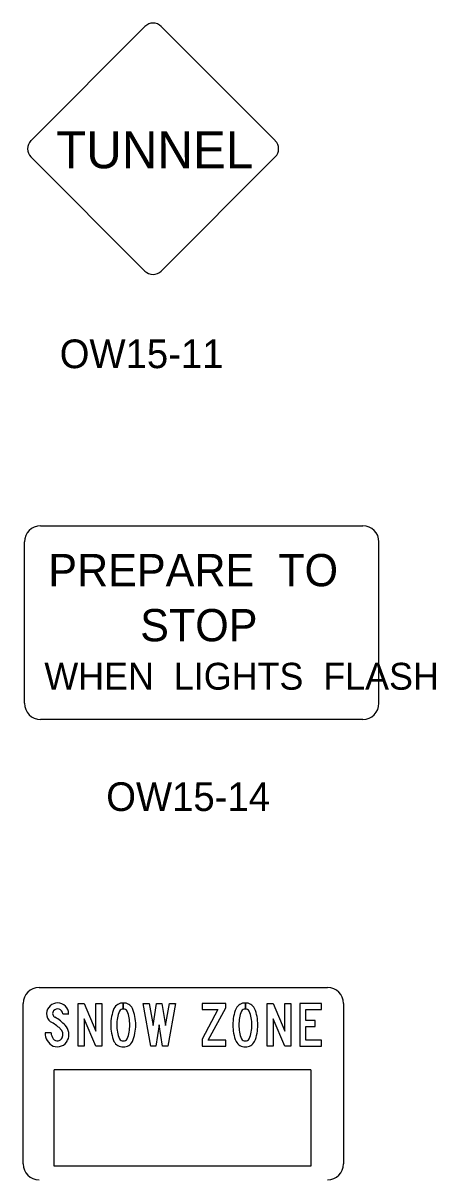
# Model space of a CAD drawing. Extents: x 42133 to 45533, y 41351 to 47951.
# Drawn here: x 43422.4 to 43530.5, y 43897.4 to 44200.2 of the extents above; entities that cross this region are included whole.
import ezdxf

# ---------------------------------------------------------------- set-up
doc = ezdxf.new("R2010")
doc.units = 0
doc.layers.add('P_TRAF_SIGN_SignDetails', color=7, linetype='Continuous')

msp = doc.modelspace()

# ---------------------------------------------------------------- linework, layer by layer
at = {"layer": 'P_TRAF_SIGN_SignDetails'}
for p, q in [((43454.29, 44199.28), (43424.42, 44169.4)), ((43488.43, 44169.41), (43458.56, 44199.29)), ((43424.42, 44165.14), (43454.29, 44135.27)), ((43458.56, 44135.27), (43488.43, 44165.14)), ((43426.94, 44068.61), (43511.39, 44068.61)), ((43422.71, 44022.16), (43422.71, 44064.39)), ((43515.62, 44022.16), (43515.62, 44064.39)), ((43511.39, 44017.94), (43426.94, 44017.94)), ((43448.61, 43942.16), (43448.61, 43943.73)), ((43448.61, 43943.73), (43448.61, 43942.16)), ((43480.6, 43942.16), (43480.6, 43943.73)), ((43480.6, 43943.73), (43480.6, 43942.16)), ((43432.75, 43940.9), (43434.3, 43940.9)), ((43429.74, 43935.93), (43428.15, 43935.93)), ((43430.5, 43901.02), (43430.5, 43926.22)), ((43497.78, 43926.22), (43430.5, 43926.22)), ((43497.78, 43926.22), (43497.78, 43901.02)), ((43497.78, 43901.02), (43430.5, 43901.02))]:
    msp.add_line(p, q, dxfattribs=at)
for points in [[(43426.54, 43947.8), (43502.14, 43947.8)], [(43422.36, 43901.62), (43422.36, 43943.62)], [(43506.33, 43943.62), (43506.33, 43901.62)]]:
    msp.add_lwpolyline(points, dxfattribs=at)
for points in [[(43438.32, 43943.59), (43441.4, 43936.4), (43441.4, 43943.59), (43442.96, 43943.59), (43442.96, 43932.43), (43441.4, 43932.43), (43438.33, 43939.6), (43438.33, 43932.43), (43436.77, 43932.43), (43436.77, 43943.59)], [(43456.41, 43937.8), (43457.35, 43943.59), (43458.72, 43943.59), (43459.65, 43937.8), (43460.69, 43943.59), (43462.28, 43943.59), (43460.27, 43932.43), (43458.92, 43932.43), (43458.03, 43938.01), (43457.14, 43932.43), (43455.8, 43932.43), (43453.79, 43943.59), (43455.38, 43943.59)], [(43469.25, 43932.43), (43475.46, 43932.43), (43475.46, 43933.98), (43470.88, 43933.98), (43475.46, 43942.48), (43475.46, 43943.59), (43469.25, 43943.59), (43469.25, 43942.03), (43473.43, 43942.03), (43469.25, 43934.27)], [(43487.85, 43943.59), (43490.92, 43936.4), (43490.92, 43943.59), (43492.48, 43943.59), (43492.48, 43932.43), (43490.92, 43932.43), (43487.85, 43939.6), (43487.85, 43932.43), (43486.29, 43932.43), (43486.29, 43943.59)], [(43496.44, 43933.98), (43496.44, 43937.56), (43498.89, 43937.56), (43498.89, 43939.12), (43496.44, 43939.12), (43496.44, 43942.03), (43500.57, 43942.03), (43500.57, 43943.59), (43494.88, 43943.59), (43494.88, 43932.43), (43500.57, 43932.43), (43500.57, 43933.98)]]:
    msp.add_lwpolyline(points, close=True, dxfattribs=at)
for centre, radius, start, end in [((43456.42, 44197.15), 3.02, 45.0254, 135), ((43426.55, 44167.27), 3.02, 135, 225.0178), ((43486.29, 44167.27), 3.02, 315, 44.9836), ((43456.42, 44137.4), 3.02, 224.9867, 315), ((43426.94, 44064.39), 4.22, 90, 180), ((43511.4, 44064.39), 4.22, 360, 90), ((43426.94, 44022.16), 4.22, 180, 270), ((43511.4, 44022.16), 4.22, 270, 360)]:
    msp.add_arc(centre, radius, start, end, dxfattribs=at)
for centre, major_axis, start_param, end_param in [((43426.54, 43943.62), (0, 4.18), 0, 1.570796), ((43502.14, 43943.62), (0, 4.18), 4.712389, 6.283185), ((43431.4, 43940.84), (0, 2.9), 4.73627, 7.790599), ((43448.52, 43941.1), (0, 2.63), 6.248251, 7.383944), ((43448.7, 43941.1), (0, 2.63), 5.182416, 6.317896), ((43480.51, 43941.1), (0, 2.63), 6.248251, 7.383944), ((43480.69, 43941.1), (0, 2.63), 5.182416, 6.317896), ((43431.11, 43940.93), (0, 2.6), 1.534839, 2.511776), ((43431.22, 43940.97), (0, -1.12), 4.015389, 5.798568), ((43431.39, 43940.8), (0, 1.36), 4.786897, 7.14073), ((43425.55, 43930.58), (0, 10.72), 5.462884, 5.78224), ((43455.94, 43938.2), (0, 10.59), 1.174165, 1.590428), ((43455.25, 43938.37), (0, -8.32), 4.311204, 4.757716), ((43448.55, 43941.03), (0, 1.13), 6.229614, 7.308112), ((43448.67, 43941.03), (0, 1.13), 5.258302, 6.336306), ((43441.98, 43938.37), (0, 8.32), 4.667047, 5.11356), ((43441.28, 43938.2), (0, -10.59), 1.551178, 1.96744), ((43487.93, 43938.2), (0, 10.59), 1.174165, 1.590428), ((43487.24, 43938.37), (0, -8.32), 4.311204, 4.757716), ((43480.54, 43941.03), (0, 1.13), 6.229614, 7.308112), ((43480.66, 43941.03), (0, 1.13), 5.258302, 6.336306), ((43473.97, 43938.37), (0, 8.32), 4.667047, 5.11356), ((43473.27, 43938.2), (0, -10.59), 1.551178, 1.96744), ((43424.19, 43928.87), (0, 11.32), 5.515139, 5.786987), ((43430.88, 43935.47), (0, 1.93), 4.254401, 5.63239), ((43430.91, 43935.47), (0, -3.46), 1.119396, 2.344165), ((43455.94, 43937.78), (0, 10.59), 1.551165, 1.967428), ((43455.25, 43937.61), (0, -8.32), 4.66706, 5.113572), ((43441.98, 43937.61), (0, 8.32), 4.311221, 4.757733), ((43441.28, 43937.78), (0, -10.59), 1.174152, 1.590415), ((43487.93, 43937.78), (0, 10.59), 1.551165, 1.967428), ((43487.24, 43937.61), (0, -8.32), 4.66706, 5.113572), ((43473.97, 43937.61), (0, 8.32), 4.311221, 4.757733), ((43473.27, 43937.78), (0, -10.59), 1.174152, 1.590415), ((43431.8, 43935.76), (0, 3.65), 1.526377, 2.701695), ((43431.95, 43935.82), (0, -2.22), 4.666332, 5.423713), ((43431.3, 43935.31), (0, -3.04), 5.927636, 7.39328), ((43431.36, 43935.27), (0, -1.42), 5.403388, 7.371662), ((43448.55, 43934.95), (0, -1.13), 5.258258, 6.336757), ((43448.67, 43934.95), (0, -1.13), 6.229591, 7.30809), ((43480.54, 43934.95), (0, -1.13), 5.258258, 6.336757), ((43480.66, 43934.95), (0, -1.13), 6.229591, 7.30809), ((43448.52, 43934.88), (0, -2.63), 5.182409, 6.318103), ((43448.7, 43934.88), (0, -2.63), 6.248268, 7.383961), ((43480.51, 43934.88), (0, -2.63), 5.182409, 6.318103), ((43480.69, 43934.88), (0, -2.63), 6.248268, 7.383961), ((43426.54, 43901.62), (0, -4.18), 4.712389, 6.283185), ((43502.14, 43901.62), (0, 4.18), 3.141593, 4.712389)]:
    msp.add_ellipse(centre, major_axis=major_axis, ratio=0.9996, start_param=start_param, end_param=end_param, dxfattribs=at)

# ---------------------------------------------------------------- texts
for s, height, p in [('TUNNEL', 9.656, (43431.01, 44162.18)), ('OW15-11', 7.5, (43431.95, 44109.87)), ('PREPARE  TO', 8.4458, (43428.96, 44052.79)), ('STOP', 8.446, (43453.04, 44038.39)), ('WHEN  LIGHTS  FLASH', 7.0269, (43427.93, 44025.73)), ('OW15-14', 7.5, (43444.14, 43993.98))]:
    msp.add_text(s, height=height, dxfattribs=at).set_placement(p)

doc.saveas('drawing.dxf')
